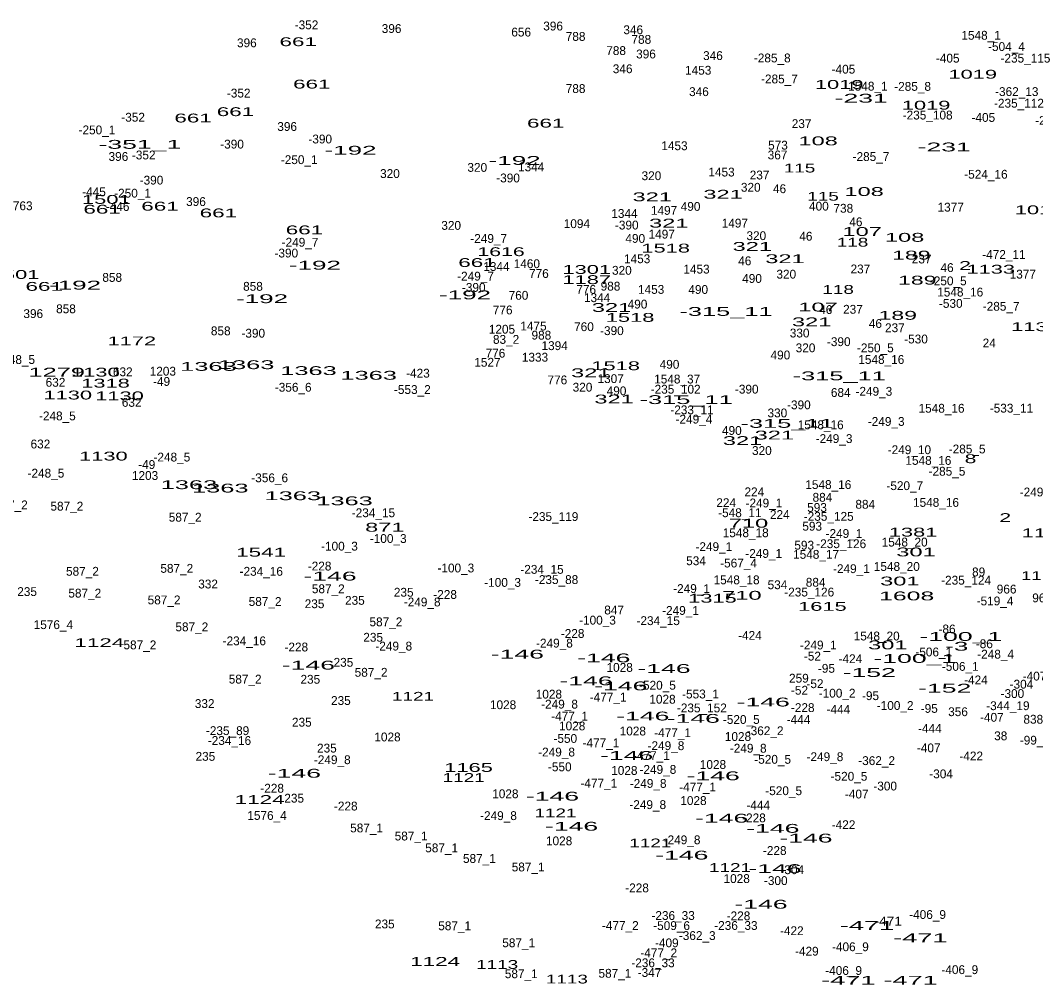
# Model space of a CAD drawing. Extents: x -660434 to -656144, y -997850 to -994016.
# Drawn here: x -659474 to -659014.2, y -995629.5 to -995192.7 of the extents above; entities that cross this region are included whole.
import ezdxf
from ezdxf.enums import TextEntityAlignment as Align

# ---------------------------------------------------------------- set-up
doc = ezdxf.new("R2010")
doc.units = 0
doc.header["$LTSCALE"] = 1.6
doc.layers.add('24', color=7, linetype='Continuous')

msp = doc.modelspace()

# ---------------------------------------------------------------- texts
at = {"layer": '24'}
for s, p in [('-352', (-659344.435, -995196.73)), ('396', (-659305.918, -995198.42)), ('396', (-659232.768, -995197.27)), ('346', (-659196.487, -995198.96)), ('656', (-659247.228, -995200.01)), ('788', (-659222.583, -995201.98)), ('788', (-659192.823, -995203.32)), ('1548_1', (-659038.957, -995201.47)), ('396', (-659371.458, -995204.88)), ('788', (-659204.243, -995208.41)), ('-504_4', (-659027.465, -995206.59)), ('396', (-659190.718, -995209.94)), ('346', (-659160.387, -995210.68)), ('-285_8', (-659133.532, -995211.74)), ('-405', (-659054.073, -995211.83)), ('-235_115', (-659018.869, -995211.82)), ('346', (-659201.287, -995216.63)), ('1453', (-659167.064, -995217.31)), ('-405', (-659101.303, -995216.82)), ('-285_7', (-659130.288, -995221.25)), ('788', (-659222.583, -995225.6)), ('346', (-659166.727, -995227)), ('1548_1', (-659090.227, -995224.52)), ('-285_8', (-659069.982, -995224.61)), ('-362_13', (-659022.811, -995226.98)), ('-352', (-659375.155, -995227.65)), ('-235_112', (-659021.809, -995232.23)), ('-352', (-659422.965, -995238.59)), ('-235_108', (-659063.159, -995237.61)), ('-405', (-659037.943, -995238.68)), ('-235_109', (-659003.195, -995240)), ('-250_1', (-659439.34, -995244.33)), ('396', (-659353.208, -995242.79)), ('237', (-659120.243, -995241.49)), ('-390', (-659338.234, -995248.45)), ('-390', (-659378.164, -995250.76)), ('1453', (-659177.814, -995251.5)), ('573', (-659130.943, -995251.24)), ('396', (-659429.628, -995256.37)), ('-352', (-659418.175, -995255.69)), ('-250_1', (-659347.76, -995257.81)), ('367', (-659131.138, -995255.67)), ('-285_7', (-659088.818, -995256.4)), ('320', (-659306.661, -995264.11)), ('320', (-659267.111, -995261.3)), ('1344', (-659242.709, -995261.07)), ('1453', (-659156.504, -995263.41)), ('-390', (-659414.644, -995267.08)), ('-390', (-659253.174, -995266.1)), ('320', (-659188.251, -995265.08)), ('237', (-659139.273, -995264.76)), ('-524_16', (-659036.765, -995264.42)), ('-445', (-659440.683, -995272.37)), ('-250_1', (-659423.22, -995272.99)), ('320', (-659143.271, -995270.32)), ('46', (-659130.227, -995270.97)), ('396', (-659394.498, -995276.79)), ('763', (-659472.958, -995278.69)), ('-446', (-659429.979, -995279.01)), ('1344', (-659200.469, -995282.19)), ('1497', (-659182.535, -995280.78)), ('490', (-659170.521, -995278.97)), ('400', (-659112.409, -995278.86)), ('738', (-659101.343, -995279.83)), ('1377', (-659052.721, -995279.31)), ('1094', (-659222.014, -995286.8)), ('1497', (-659150.475, -995286.55)), ('46', (-659095.657, -995285.95)), ('320', (-659278.931, -995287.58)), ('-390', (-659199.424, -995287.43)), ('1497', (-659183.595, -995291.54)), ('-249_7', (-659347.388, -995295.22)), ('-249_7', (-659261.948, -995293.49)), ('490', (-659195.571, -995293.47)), ('320', (-659140.751, -995292.24)), ('46', (-659118.317, -995292.48)), ('-390', (-659353.594, -995300.1)), ('-472_11', (-659028.619, -995300.74)), ('1460', (-659244.664, -995304.94)), ('1453', (-659194.714, -995302.69)), ('46', (-659145.967, -995303.62)), ('237', (-659065.883, -995302.8)), ('1344', (-659258.449, -995306.21)), ('776', (-659239.203, -995309.37)), ('320', (-659201.631, -995307.93)), ('1453', (-659167.834, -995307.37)), ('320', (-659127.181, -995309.67)), ('237', (-659093.623, -995307.32)), ('46', (-659054.377, -995306.7)), ('1377', (-659020.071, -995309.66)), ('858', (-659432.437, -995311.14)), ('-249_7', (-659267.898, -995310.58)), ('490', (-659142.681, -995311.62)), ('-250_5', (-659053.826, -995312.71)), ('858', (-659368.687, -995315.18)), ('-390', (-659268.724, -995315.66)), ('760', (-659248.442, -995319.25)), ('776', (-659217.783, -995316.57)), ('988', (-659206.783, -995315.11)), ('1453', (-659188.374, -995316.57)), ('490', (-659167.061, -995316.61)), ('1548_16', (-659048.411, -995317.78)), ('1344', (-659212.849, -995320.32)), ('490', (-659194.551, -995323.24)), ('-530', (-659052.679, -995322.91)), ('396', (-659468.188, -995327.55)), ('858', (-659453.367, -995325.36)), ('776', (-659255.613, -995325.89)), ('46', (-659109.297, -995325.71)), ('237', (-659096.983, -995325.59)), ('-285_7', (-659029.878, -995324.22)), ('46', (-659086.827, -995332.05)), ('858', (-659383.287, -995335.35)), ('-390', (-659368.564, -995336.42)), ('1205', (-659255.934, -995334.61)), ('1475', (-659241.66, -995333.17)), ('988', (-659238.083, -995337.3)), ('760', (-659218.802, -995333.46)), ('-390', (-659206.144, -995335.26)), ('330', (-659121.131, -995336.33)), ('237', (-659077.993, -995333.94)), ('83_2', (-659254.055, -995339.22)), ('1394', (-659232.07, -995342.05)), ('-390', (-659103.424, -995340.25)), ('-530', (-659068.429, -995339.04)), ('24', (-659035.271, -995340.84)), ('776', (-659258.883, -995345.48)), ('490', (-659129.841, -995346.28)), ('320', (-659118.461, -995343.03)), ('-250_5', (-659086.856, -995343.06)), ('-248_5', (-659475.697, -995348.34)), ('1527', (-659262.506, -995349.59)), ('1333', (-659240.98, -995347.29)), ('490', (-659180.051, -995350.51)), ('1548_16', (-659084.141, -995348.32)), ('632', (-659427.643, -995353.91)), ('1203', (-659409.504, -995353.62)), ('-423', (-659293.979, -995354.53)), ('632', (-659458.123, -995358.65)), ('-49', (-659410.075, -995358.26)), ('776', (-659230.843, -995357.57)), ('1307', (-659206.7, -995356.99)), ('1548_37', (-659176.587, -995357.18)), ('-356_6', (-659350.473, -995360.9)), ('-553_2', (-659296.512, -995361.93)), ('320', (-659219.461, -995360.87)), ('490', (-659204.051, -995362.52)), ('-235_102', (-659177.279, -995361.79)), ('-390', (-659145.084, -995361.76)), ('684', (-659102.517, -995363.27)), ('-249_3', (-659087.512, -995362.74)), ('632', (-659423.613, -995367.74)), ('-390', (-659121.474, -995368.87)), ('-248_5', (-659457.267, -995373.88)), ('-233_11', (-659169.879, -995371.12)), ('330', (-659131.211, -995372.52)), ('1548_16', (-659056.871, -995370.41)), ('-533_11', (-659025.219, -995370.36)), ('-249_4', (-659168.996, -995375.33)), ('1548_16', (-659111.591, -995377.9)), ('-249_3', (-659081.942, -995376.38)), ('490', (-659151.831, -995380.47)), ('632', (-659464.943, -995386.6)), ('-249_3', (-659105.552, -995384.16)), ('-248_5', (-659405.417, -995392.52)), ('320', (-659138.231, -995389.58)), ('-249_10', (-659071.429, -995389.19)), ('-285_5', (-659045.282, -995388.86)), ('-49', (-659416.795, -995395.91)), ('1548_16', (-659062.821, -995394.03)), ('-248_5', (-659462.447, -995399.81)), ('1203', (-659417.564, -995400.87)), ('-356_6', (-659361.123, -995401.91)), ('-285_5', (-659054.402, -995398.94)), ('1548_16', (-659108.141, -995404.98)), ('-520_7', (-659073.512, -995405.47)), ('224', (-659141.641, -995408.28)), ('884', (-659110.811, -995410.74)), ('-249_9', (-659013.138, -995408.34)), ('587_2', (-659478.12, -995414.18)), ('587_2', (-659452.96, -995414.76)), ('224', (-659154.401, -995413.18)), ('-249_1', (-659137.306, -995413.32)), ('593', (-659113.253, -995415.34)), ('884', (-659091.411, -995413.91)), ('1548_16', (-659059.371, -995413.05)), ('587_2', (-659399.39, -995419.75)), ('-234_15', (-659314.139, -995417.74)), ('-235_119', (-659232.645, -995419.48)), ('-548_11', (-659148.213, -995417.73)), ('224', (-659130.121, -995418.55)), ('-235_125', (-659107.965, -995419.37)), ('593', (-659115.453, -995423.84)), ('-100_3', (-659307.444, -995429.41)), ('1548_18', (-659145.556, -995426.81)), ('-249_1', (-659101.056, -995427.14)), ('-100_3', (-659329.524, -995432.87)), ('-249_1', (-659159.976, -995433.1)), ('593', (-659119.063, -995432.44)), ('-235_126', (-659102.301, -995431.77)), ('1548_20', (-659073.576, -995431.03)), ('-249_1', (-659137.406, -995436.18)), ('1548_17', (-659113.671, -995436.58)), ('587_2', (-659403.19, -995442.92)), ('-228', (-659338.515, -995441.89)), ('-100_3', (-659276.814, -995442.76)), ('-234_15', (-659237.809, -995443.38)), ('534', (-659168.041, -995439.48)), ('-567_4', (-659148.788, -995440.51)), ('-249_1', (-659097.696, -995443.08)), ('1548_20', (-659077.126, -995442.07)), ('587_2', (-659445.91, -995444.26)), ('-234_16', (-659364.935, -995444.27)), ('-235_88', (-659231.201, -995448.02)), ('89', (-659040.073, -995444.55)), ('332', (-659389.017, -995450.02)), ('587_2', (-659334.59, -995452.18)), ('-100_3', (-659255.644, -995449.29)), ('-249_1', (-659170.086, -995452.09)), ('1548_18', (-659149.676, -995448.13)), ('534', (-659131.171, -995450.35)), ('884', (-659113.881, -995449.23)), ('-235_124', (-659045.749, -995448.29)), ('966', (-659027.403, -995452.32)), ('235', (-659470.977, -995453.46)), ('587_2', (-659444.85, -995454.15)), ('587_2', (-659408.95, -995457.23)), ('235', (-659300.427, -995453.76)), ('-228', (-659281.675, -995454.76)), ('-235_126', (-659116.791, -995453.66)), ('966', (-659011.333, -995456.3)), ('587_2', (-659363.2, -995457.94)), ('235', (-659340.797, -995458.95)), ('235', (-659322.537, -995457.42)), ('-249_8', (-659292.072, -995458.16)), ('847', (-659205.137, -995461.79)), ('-519_4', (-659032.646, -995457.69)), ('-100_3', (-659212.674, -995466.38)), ('-249_1', (-659175.076, -995461.99)), ('1576_4', (-659459.074, -995468.42)), ('587_2', (-659396.37, -995469.42)), ('587_2', (-659308.48, -995467.16)), ('-234_15', (-659185.199, -995466.62)), ('-86', (-659054.38, -995470.4)), ('235', (-659314.267, -995474.15)), ('-228', (-659223.935, -995472.41)), ('-424', (-659143.643, -995473.3)), ('1548_20', (-659086.246, -995473.57)), ('587_2', (-659419.89, -995477.59)), ('-234_16', (-659372.615, -995475.77)), ('-228', (-659349.075, -995478.56)), ('-249_8', (-659304.942, -995478.14)), ('-249_8', (-659232.172, -995476.79)), ('-249_1', (-659112.676, -995477.64)), ('-86', (-659037.5, -995477.08)), ('-52', (-659115.345, -995482.68)), ('-424', (-659098.143, -995483.86)), ('-506_1', (-659060.396, -995480.8)), ('-248_4', (-659032.381, -995481.8)), ('235', (-659327.727, -995485.49)), ('1028', (-659202.624, -995487.8)), ('-95', (-659108.99, -995488.21)), ('-506_1', (-659048.396, -995487.33)), ('587_2', (-659372.22, -995493.1)), ('235', (-659342.717, -995493.18)), ('587_2', (-659315.2, -995490.02)), ('259', (-659121.463, -995492.7)), ('-424', (-659041.303, -995493.47)), ('-407', (-659014.769, -995491.72)), ('-520_5', (-659185.526, -995495.87)), ('-52', (-659121.195, -995498.14)), ('-52', (-659114.195, -995495.16)), ('-304', (-659020.693, -995495.4)), ('235', (-659328.877, -995502.8)), ('1028', (-659234.694, -995499.9)), ('-477_1', (-659207.852, -995501.24)), ('1028', (-659183.234, -995502.2)), ('-553_1', (-659166.036, -995499.84)), ('-100_2', (-659104.164, -995499.47)), ('-95', (-659089.03, -995500.6)), ('-300', (-659024.793, -995499.65)), ('332', (-659390.557, -995504.18)), ('1028', (-659255.424, -995504.7)), ('-249_8', (-659229.862, -995504.43)), ('-235_152', (-659165.415, -995506.15)), ('-228', (-659119.735, -995506.01)), ('-444', (-659103.577, -995506.76)), ('-100_2', (-659077.884, -995505.04)), ('-95', (-659062.43, -995506.36)), ('356', (-659049.413, -995507.86)), ('-344_19', (-659026.829, -995505.14)), ('-477_1', (-659225.322, -995509.88)), ('-520_5', (-659147.556, -995511.38)), ('-444', (-659121.627, -995511.37)), ('-407', (-659034.079, -995510.4)), ('838', (-659015.317, -995511.28)), ('-235_89', (-659380.197, -995516.44)), ('235', (-659346.567, -995512.61)), ('1028', (-659224.134, -995514.3)), ('1028', (-659196.674, -995516.61)), ('-362_2', (-659136.768, -995516.48)), ('-444', (-659062.157, -995515.4)), ('-234_16', (-659379.335, -995520.9)), ('1028', (-659307.774, -995519.3)), ('-550', (-659227.249, -995519.96)), ('-477_1', (-659178.662, -995517.37)), ('1028', (-659149.054, -995519.1)), ('38', (-659030.057, -995518.78)), ('-99_3', (-659014.593, -995520.77)), ('235', (-659335.217, -995524.34)), ('-249_8', (-659231.212, -995526.13)), ('-477_1', (-659211.112, -995521.98)), ('-249_8', (-659181.672, -995523.25)), ('-249_8', (-659144.422, -995524.4)), ('-407', (-659062.689, -995524.24)), ('235', (-659390.237, -995528.08)), ('-249_8', (-659332.782, -995529.61)), ('-477_1', (-659188.262, -995527.74)), ('-520_5', (-659133.346, -995529.43)), ('-249_8', (-659109.672, -995528.24)), ('-362_2', (-659086.268, -995530.02)), ('-422', (-659043.449, -995527.92)), ('-550', (-659229.749, -995532.83)), ('1028', (-659200.514, -995534.47)), ('-249_8', (-659185.322, -995534)), ('1028', (-659160.384, -995531.78)), ('-520_5', (-659098.786, -995537.12)), ('-304', (-659057.073, -995536.02)), ('-228', (-659360.015, -995542.52)), ('-477_1', (-659212.072, -995540.23)), ('-249_8', (-659189.732, -995540.34)), ('-477_1', (-659167.332, -995541.96)), ('-520_5', (-659128.356, -995543.65)), ('-300', (-659082.403, -995541.53)), ('235', (-659350.027, -995547.03)), ('1028', (-659254.394, -995545.03)), ('1028', (-659169.214, -995548.11)), ('-407', (-659095.279, -995545.15)), ('-228', (-659326.665, -995550.59)), ('-249_8', (-659189.922, -995549.95)), ('-444', (-659139.867, -995550.17)), ('1576_4', (-659362.304, -995554.85)), ('-249_8', (-659257.512, -995554.94)), ('-228', (-659141.815, -995555.95)), ('587_1', (-659317.234, -995560.52)), ('-422', (-659101.249, -995559.04)), ('587_1', (-659297.074, -995564.17)), ('1028', (-659230.054, -995566.35)), ('-249_8', (-659174.372, -995565.89)), ('587_1', (-659283.244, -995569.54)), ('-228', (-659132.405, -995570.74)), ('587_1', (-659266.154, -995574.35)), ('587_1', (-659244.074, -995578.19)), ('-304', (-659124.473, -995579.43)), ('1028', (-659149.634, -995583.45)), ('-300', (-659131.943, -995584.36)), ('-228', (-659194.755, -995587.66)), ('-406_9', (-659063.192, -995599.73)), ('235', (-659308.997, -995604)), ('-236_33', (-659178.427, -995600.18)), ('-228', (-659148.825, -995600.32)), ('587_1', (-659277.354, -995604.84)), ('-477_2', (-659202.338, -995604.7)), ('-509_6', (-659179.117, -995604.75)), ('-236_33', (-659150.007, -995604.69)), ('-422', (-659124.669, -995607.06)), ('587_1', (-659248.354, -995612.53)), ('-409', (-659181.279, -995612.55)), ('-362_3', (-659167.508, -995609.27)), ('-477_2', (-659184.948, -995617.08)), ('-429', (-659117.865, -995616.34)), ('-406_9', (-659098.142, -995614.33)), ('-236_33', (-659187.537, -995621.6)), ('587_1', (-659247.204, -995626.55)), ('587_1', (-659204.774, -995626.35)), ('-347', (-659189.115, -995625.99)), ('-406_9', (-659101.212, -995625.09)), ('-406_9', (-659048.602, -995624.7))]:
    msp.add_text(s, height=4, dxfattribs=at).set_placement(p, align=Align.CENTER)
for s, width, p in [('661', 1.9, (-659348.197, -995204.37)), ('1019', 1.85, (-659042.745, -995219.11)), ('661', 1.9, (-659342.047, -995223.58)), ('1019', 1.85, (-659103.225, -995223.72)), ('-231', 2.25, (-659093.251, -995229.97)), ('661', 1.9, (-659376.607, -995236.06)), ('1019', 1.85, (-659063.865, -995233.13)), ('661', 1.9, (-659395.807, -995238.94)), ('661', 1.9, (-659236.117, -995241.25)), ('108', 2, (-659112.754, -995249.29)), ('-351_1', 2.25, (-659419.897, -995250.87)), ('-192', 2.2, (-659324.515, -995253.55)), ('-231', 2.25, (-659055.671, -995252.06)), ('-192', 2.2, (-659250.205, -995258.16)), ('115', 1.6, (-659121.184, -995261.61)), ('108', 2, (-659091.924, -995272.25)), ('1501', 1.85, (-659435.11, -995275.81)), ('321', 2, (-659187.877, -995274.63)), ('321', 2, (-659155.807, -995273.47)), ('115', 1.6, (-659110.534, -995274.38)), ('661', 1.9, (-659436.997, -995280.25)), ('661', 1.9, (-659410.787, -995278.89)), ('661', 1.9, (-659384.347, -995281.93)), ('1018', 1.85, (-659012.69, -995280.52)), ('321', 2, (-659180.387, -995286.54)), ('661', 1.9, (-659345.367, -995289.62)), ('107', 2, (-659092.819, -995290.36)), ('118', 1.6, (-659097.164, -995295.19)), ('108', 2, (-659073.584, -995292.99)), ('1616', 1.8, (-659256.333, -995299.48)), ('1518', 1.85, (-659181.784, -995297.87)), ('321', 2, (-659142.567, -995297.1)), ('661', 1.9, (-659267.227, -995304.41)), ('321', 2, (-659127.777, -995302.67)), ('189', 1.95, (-659070.553, -995301.05)), ('1501', 1.85, (-659476.4, -995309.81)), ('-192', 2.2, (-659340.645, -995305.61)), ('1301', 1.85, (-659217.55, -995307.54)), ('2', 1.8, (-659046.231, -995305.73)), ('1133', 1.85, (-659034.594, -995307.44)), ('-192', 2.2, (-659449.255, -995314.64)), ('1187', 1.85, (-659217.539, -995312.16)), ('189', 1.95, (-659067.863, -995312.38)), ('661', 1.9, (-659463.217, -995315.2)), ('-192', 2.2, (-659272.665, -995319.05)), ('118', 1.6, (-659103.694, -995316.6)), ('-192', 2.2, (-659364.585, -995320.78)), ('321', 2, (-659206.307, -995324.75)), ('-315_11', 2.15, (-659154.474, -995326.55)), ('107', 2, (-659112.789, -995324.55)), ('189', 1.95, (-659076.693, -995328.32)), ('1518', 1.85, (-659197.914, -995329.25)), ('321', 2, (-659115.687, -995331.27)), ('1133', 1.85, (-659014.364, -995333.46)), ('1172', 1.85, (-659423.549, -995339.91)), ('1363', 2.15, (-659388.863, -995351.44)), ('1363', 2.15, (-659371.773, -995350.67)), ('1518', 1.85, (-659204.444, -995351.15)), ('1279', 2.15, (-659457.557, -995354.04)), ('1130', 1.85, (-659440.08, -995354.04)), ('1363', 2.15, (-659343.543, -995353.36)), ('1363', 2.15, (-659316.283, -995355.48)), ('321', 2, (-659215.717, -995354.34)), ('-315_11', 2.15, (-659103.204, -995355.74)), ('1318', 1.85, (-659435.454, -995359.04)), ('1130', 1.85, (-659452.56, -995364.41)), ('1130', 1.85, (-659429.13, -995364.8)), ('321', 2, (-659205.157, -995366.23)), ('-315_11', 2.15, (-659172.524, -995366.5)), ('-315_11', 2.15, (-659126.824, -995377.26)), ('321', 2, (-659132.577, -995382.55)), ('321', 2, (-659146.977, -995385.05)), ('1130', 1.85, (-659436.43, -995392.07)), ('8', 1.8, (-659043.731, -995393.27)), ('1363', 2.15, (-659397.693, -995405.03)), ('1363', 2.15, (-659383.483, -995406.57)), ('1363', 2.15, (-659350.653, -995410.03)), ('1363', 2.15, (-659327.223, -995412.33)), ('2', 1.8, (-659028.031, -995419.94)), ('871', 2, (-659308.973, -995424.3)), ('710', 2, (-659144.299, -995422.49)), ('1381', 1.85, (-659069.754, -995426.51)), ('1133', 1.85, (-659009.564, -995426.86)), ('1541', 1.9, (-659364.999, -995435.61)), ('301', 2, (-659068.434, -995435.5)), ('-146', 2.25, (-659333.791, -995446.43)), ('1116', 1.55, (-659011.615, -995446.21)), ('301', 2, (-659075.754, -995448.66)), ('1315', 1.85, (-659160.614, -995456.46)), ('710', 2, (-659147.279, -995455.14)), ('1608', 2.1, (-659072.659, -995455.42)), ('1615', 1.85, (-659110.809, -995460.15)), ('-100_1', 2.25, (-659048.14, -995473.79)), ('1124', 1.9, (-659438.259, -995476.6)), ('301', 2, (-659081.204, -995477.6)), ('-3', 2.2, (-659049.974, -995478.21)), ('-146', 2.25, (-659248.951, -995481.77)), ('-146', 2.25, (-659209.811, -995483.5)), ('-100_1', 2.25, (-659068.97, -995483.73)), ('-146', 2.25, (-659343.591, -995486.76)), ('-146', 2.25, (-659182.551, -995488.3)), ('-146', 2.25, (-659217.881, -995493.87)), ('-152', 2.25, (-659089.601, -995490.12)), ('-146', 2.25, (-659202.131, -995496.18)), ('-152', 2.25, (-659055.431, -995497.22)), ('1121', 1.6, (-659296.21, -995500.88)), ('-146', 2.25, (-659137.621, -995503.47)), ('-146', 2.25, (-659192.151, -995509.81)), ('-146', 2.25, (-659169.301, -995510.88)), ('-146', 2.25, (-659199.451, -995527.68)), ('1165', 1.85, (-659271.049, -995533.12)), ('-146', 2.25, (-659349.921, -995535.74)), ('1121', 1.6, (-659273.27, -995537.66)), ('-146', 2.25, (-659160.281, -995536.9)), ('1124', 1.9, (-659365.679, -995547.65)), ('-146', 2.25, (-659233.051, -995546.12)), ('1121', 1.6, (-659231.69, -995553.7)), ('-146', 2.25, (-659156.441, -995556.1)), ('-146', 2.25, (-659224.411, -995559.75)), ('-146', 2.25, (-659133.261, -995560.69)), ('1121', 1.6, (-659188.76, -995567.31)), ('-146', 2.25, (-659118.281, -995565.11)), ('-146', 2.25, (-659174.491, -995572.81)), ('1121', 1.6, (-659152.66, -995578.45)), ('-146', 2.25, (-659132.301, -995578.94)), ('-146', 2.25, (-659138.641, -995595.07)), ('-471', 1.15, (-659081, -995602.7)), ('-471', 2.3, (-659090.621, -995604.73)), ('-471', 2.3, (-659066.471, -995610.3)), ('1124', 1.9, (-659286.189, -995620.97)), ('1113', 1.6, (-659258.11, -995622.34)), ('1113', 1.6, (-659226.52, -995628.96)), ('-471', 2.3, (-659099.071, -995629.51)), ('-471', 2.3, (-659070.881, -995629.51))]:
    msp.add_text(s, height=4, dxfattribs=dict(at, width=width)).set_placement(p, align=Align.CENTER)

doc.saveas('drawing.dxf')
